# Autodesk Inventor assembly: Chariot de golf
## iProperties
Author: Philippe Jeannerod
Subject: Motoréducteur
Title: Chariot de golf
Company: Lycée Edgar Faure - Morteau
Shininess: 64.0
Length Units: 11269
Angle Units: 11279
Time Units: 11290
Mass Units: 11283
Length Display Precision: 3
Angle Display Precision: 2
Compacted: True
Created: 2003-05
Part Number: Motoréducteur
Document SubType Name: Assembly
Designer: Philippe Jeannerod
Density: 0.0
Volumn: 0.0
Area: 0.0
PropertySet Name: Model Information
Control State: 0
Master: False
Checked Out: False
